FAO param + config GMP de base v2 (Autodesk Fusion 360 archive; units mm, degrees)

design "FAO param + config GMP de base" references "brut conf 1", "Configuration 2", "Configuration 1", "brut conf 2", "brut conf 3", "Configuration 3"
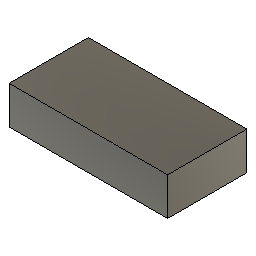
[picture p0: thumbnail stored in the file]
component_insert "Insertion d'un composant1"
component_insert "Insertion d'un composant2"
component_insert "Insertion d'un composant3"
component_insert "Insertion d'un composant4"
component_insert "Insertion d'un composant5"
component_insert "Insertion d'un composant6"

design "Configuration 2"
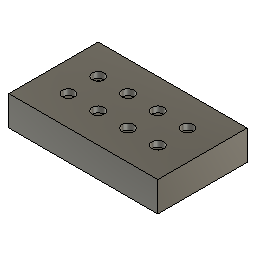
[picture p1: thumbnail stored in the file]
parameter "longueur" = 100
parameter "largeur" = 60
parameter "hauteurext" = 20
parameter "dlamage" = 8
sketch "Esquisse1" plane through (0, 0, 0) normal (0, 0, 1) x axis (1, 0, 0)
  line L1 (-50, -30) -> (50, -30)
  line L2 (-50, 30) -> (-50, -30)
  line L3 (50, 30) -> (-50, 30)
  line L4 (50, -30) -> (50, 30)
  line L5 (-50, 30) -> (50, -30)
  line L6 (50, 30) -> (-50, -30)
  point P6 (0, 0)
  point P1 (0, 0)
  point P4 (-50, 30)
  point P5 (50, 30)
  point P3 (-50, -30)
  horizontal L1
  perpendicular L1 L2
  parallel L1 L3
  parallel L2 L4
  coincident L5 P6
  coincident L6 P6
  coincident P1 P6
  dimension "d3" distance P4 P5 = 100 (= "longueur")
  dimension "d4" distance P3 P4 = 60 (= "largeur")
extrude "Extrusion" new body sketch "Esquisse1" profile of L1 L2 L3 L4 along normal blind 20 (= "hauteurext") named "hauteur"
sketch "Esquisse2" plane through (0, 0, 20) normal (0, 0, 1) x axis (-1, 0, 0)
  line L1 (50, -30) -> (-50, -30)
  line L2 (50, 30) -> (50, -30)
  point P2 (30, -10)
  dimension "d8" distance P2 L1 = 20
  dimension "d9" distance P2 L2 = 20
  dimension "d12" R-Pattern1-uDistance = -20 (= "-( longueur - 40 mm ) / ( nb_de_trous - 1 )")
  dimension "d13" R-Pattern1-vDistance = 20 (= "( largeur - 40 mm ) / ( floor(nb_de_trous) / 2 - 1 )")
hole "Perçage1" HoleDiameter 4 (= "dlamage / 2") CBDepth 4 (= "hauteurext / 5") CBDiameter 8 (= "dlamage") named "dlam"
hole "Perçage2" HoleDiameter 4 (= "dlamage / 2") CBDepth 4 (= "hauteurext / 5") CBDiameter 8 (= "dlamage")
hole "Perçage3" HoleDiameter 4 (= "dlamage / 2") CBDepth 4 (= "hauteurext / 5") CBDiameter 8 (= "dlamage")

design "brut conf 2"
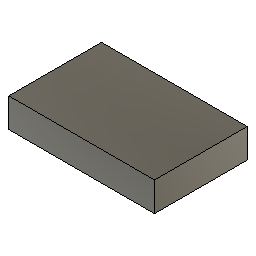
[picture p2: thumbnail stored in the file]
parameter "longueur" = 110
parameter "largeur" = 70
parameter "hauteurext" = 22
parameter "dlamage" = 10
sketch "Esquisse1" plane through (0, 0, 0) normal (0, 0, 1) x axis (1, 0, 0)
  line L1 (-55, -35) -> (55, -35)
  line L2 (-55, 35) -> (-55, -35)
  line L3 (55, 35) -> (-55, 35)
  line L4 (55, -35) -> (55, 35)
  line L5 (-55, 35) -> (55, -35)
  line L6 (55, 35) -> (-55, -35)
  point P6 (0, 0)
  point P1 (0, 0)
  point P4 (-55, 35)
  point P5 (55, 35)
  point P3 (-55, -35)
  horizontal L1
  perpendicular L1 L2
  parallel L1 L3
  parallel L2 L4
  coincident L5 P6
  coincident L6 P6
  coincident P1 P6
  dimension "d3" distance P4 P5 = 110 (= "longueur")
  dimension "d4" distance P3 P4 = 70 (= "largeur")
extrude "Extrusion" new body sketch "Esquisse1" profile of L1 L2 L3 L4 along normal blind 22 (= "hauteurext") named "hauteur"
sketch "Esquisse2" plane through (0, 0, 22) normal (0, 0, 1) x axis (-1, 0, 0)
  line L1 (55, -35) -> (-55, -35)
  line L2 (55, 35) -> (55, -35)
  point P2 (35, -15)
  dimension "d8" distance P2 L1 = 20
  dimension "d9" distance P2 L2 = 20
  dimension "d12" R-Pattern1-uDistance = -17.5 (= "-( longueur - 40 mm ) / ( nb_de_trous - 1 )")
  dimension "d13" R-Pattern1-vDistance = 20 (= "( largeur - 40 mm ) / ( floor(nb_de_trous) / 2 - 1 )")
hole "Perçage1" HoleDiameter 5 (= "dlamage / 2") CBDepth 4.4 (= "hauteurext / 5") CBDiameter 10 (= "dlamage") named "dlam"
hole "Perçage2" HoleDiameter 5 (= "dlamage / 2") CBDepth 4.4 (= "hauteurext / 5") CBDiameter 10 (= "dlamage")
hole "Perçage3" HoleDiameter 5 (= "dlamage / 2") CBDepth 4.4 (= "hauteurext / 5") CBDiameter 10 (= "dlamage")

design "Configuration 3"
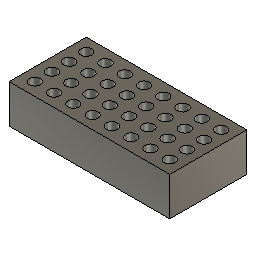
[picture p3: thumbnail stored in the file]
parameter "longueur" = 250
parameter "largeur" = 120
parameter "hauteurext" = 60
parameter "dlamage" = 17
sketch "Esquisse1" plane through (0, 0, 0) normal (0, 0, 1) x axis (1, 0, 0)
  line L1 (-125, -60) -> (125, -60)
  line L2 (-125, 60) -> (-125, -60)
  line L3 (125, 60) -> (-125, 60)
  line L4 (125, -60) -> (125, 60)
  line L5 (-125, 60) -> (125, -60)
  line L6 (125, 60) -> (-125, -60)
  point P6 (0, 0)
  point P1 (0, 0)
  point P4 (-125, 60)
  point P5 (125, 60)
  point P3 (-125, -60)
  horizontal L1
  perpendicular L1 L2
  parallel L1 L3
  parallel L2 L4
  coincident L5 P6
  coincident L6 P6
  coincident P1 P6
  dimension "d3" distance P4 P5 = 250 (= "longueur")
  dimension "d4" distance P3 P4 = 120 (= "largeur")
extrude "Extrusion" new body sketch "Esquisse1" profile of L1 L2 L3 L4 along normal blind 60 (= "hauteurext") named "hauteur"
sketch "Esquisse2" plane through (0, 0, 60) normal (0, 0, 1) x axis (-1, 0, 0)
  line L1 (125, -60) -> (-125, -60)
  line L2 (125, 60) -> (125, -60)
  point P2 (105, -40)
  dimension "d8" distance P2 L1 = 20
  dimension "d9" distance P2 L2 = 20
  dimension "d12" R-Pattern1-uDistance = -30 (= "-( longueur - 40 mm ) / ( nb_de_trous - 1 )")
  dimension "d13" R-Pattern1-vDistance = 26.6667 (= "( largeur - 40 mm ) / ( floor(nb_de_trous) / 2 - 1 )")
hole "Perçage1" HoleDiameter 8.5 (= "dlamage / 2") CBDepth 12 (= "hauteurext / 5") CBDiameter 17 (= "dlamage") named "dlam"
hole "Perçage2" HoleDiameter 8.5 (= "dlamage / 2") CBDepth 12 (= "hauteurext / 5") CBDiameter 17 (= "dlamage")
hole "Perçage3" HoleDiameter 8.5 (= "dlamage / 2") CBDepth 12 (= "hauteurext / 5") CBDiameter 17 (= "dlamage")

design "brut conf 3"
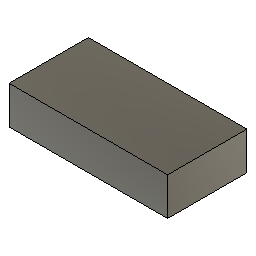
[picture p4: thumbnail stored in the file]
parameter "longueur" = 260
parameter "largeur" = 130
parameter "hauteurext" = 62
parameter "dlamage" = 10
sketch "Esquisse1" plane through (0, 0, 0) normal (0, 0, 1) x axis (1, 0, 0)
  line L1 (-130, -65) -> (130, -65)
  line L2 (-130, 65) -> (-130, -65)
  line L3 (130, 65) -> (-130, 65)
  line L4 (130, -65) -> (130, 65)
  line L5 (-130, 65) -> (130, -65)
  line L6 (130, 65) -> (-130, -65)
  point P6 (0, 0)
  point P1 (0, 0)
  point P4 (-130, 65)
  point P5 (130, 65)
  point P3 (-130, -65)
  horizontal L1
  perpendicular L1 L2
  parallel L1 L3
  parallel L2 L4
  coincident L5 P6
  coincident L6 P6
  coincident P1 P6
  dimension "d3" distance P4 P5 = 260 (= "longueur")
  dimension "d4" distance P3 P4 = 130 (= "largeur")
extrude "Extrusion" new body sketch "Esquisse1" profile of L1 L2 L3 L4 along normal blind 62 (= "hauteurext") named "hauteur"
sketch "Esquisse2" plane through (0, 0, 62) normal (0, 0, 1) x axis (-1, 0, 0)
  line L1 (130, -65) -> (-130, -65)
  line L2 (130, 65) -> (130, -65)
  point P2 (110, -45)
  dimension "d8" distance P2 L1 = 20
  dimension "d9" distance P2 L2 = 20
  dimension "d12" R-Pattern1-uDistance = -55 (= "-( longueur - 40 mm ) / ( nb_de_trous - 1 )")
  dimension "d13" R-Pattern1-vDistance = 60 (= "( largeur - 40 mm ) / ( floor(nb_de_trous) / 2 - 1 )")
hole "Perçage1" HoleDiameter 5 (= "dlamage / 2") CBDepth 12.4 (= "hauteurext / 5") CBDiameter 10 (= "dlamage") named "dlam"
hole "Perçage2" HoleDiameter 5 (= "dlamage / 2") CBDepth 12.4 (= "hauteurext / 5") CBDiameter 10 (= "dlamage")
hole "Perçage3" HoleDiameter 5 (= "dlamage / 2") CBDepth 12.4 (= "hauteurext / 5") CBDiameter 10 (= "dlamage")

design "brut conf 1"
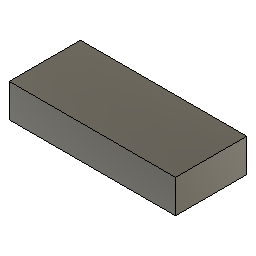
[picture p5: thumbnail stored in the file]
parameter "longueur" = 210
parameter "largeur" = 90
parameter "hauteurext" = 42
parameter "dlamage" = 10
sketch "Esquisse1" plane through (0, 0, 0) normal (0, 0, 1) x axis (1, 0, 0)
  line L1 (-105, -45) -> (105, -45)
  line L2 (-105, 45) -> (-105, -45)
  line L3 (105, 45) -> (-105, 45)
  line L4 (105, -45) -> (105, 45)
  line L5 (-105, 45) -> (105, -45)
  line L6 (105, 45) -> (-105, -45)
  point P6 (0, 0)
  point P1 (0, 0)
  point P4 (-105, 45)
  point P5 (105, 45)
  point P3 (-105, -45)
  horizontal L1
  perpendicular L1 L2
  parallel L1 L3
  parallel L2 L4
  coincident L5 P6
  coincident L6 P6
  coincident P1 P6
  dimension "d3" distance P4 P5 = 210 (= "longueur")
  dimension "d4" distance P3 P4 = 90 (= "largeur")
extrude "Extrusion" new body sketch "Esquisse1" profile of L1 L2 L3 L4 along normal blind 42 (= "hauteurext") named "hauteur"
sketch "Esquisse2" plane through (0, 0, 42) normal (0, 0, 1) x axis (-1, 0, 0)
  line L1 (105, -45) -> (-105, -45)
  line L2 (105, 45) -> (105, -45)
  point P2 (85, -25)
  dimension "d8" distance P2 L1 = 20
  dimension "d9" distance P2 L2 = 20
  dimension "d12" R-Pattern1-uDistance = -42.5 (= "-( longueur - 40 mm ) / ( nb_de_trous - 1 )")
  dimension "d13" R-Pattern1-vDistance = 33.3333 (= "( largeur - 40 mm ) / ( floor(nb_de_trous) / 2 - 1 )")
hole "Perçage1" HoleDiameter 5 (= "dlamage / 2") CBDepth 8.4 (= "hauteurext / 5") CBDiameter 10 (= "dlamage") named "dlam"
hole "Perçage2" HoleDiameter 5 (= "dlamage / 2") CBDepth 8.4 (= "hauteurext / 5") CBDiameter 10 (= "dlamage")
hole "Perçage3" HoleDiameter 5 (= "dlamage / 2") CBDepth 8.4 (= "hauteurext / 5") CBDiameter 10 (= "dlamage")

design "Configuration 1"
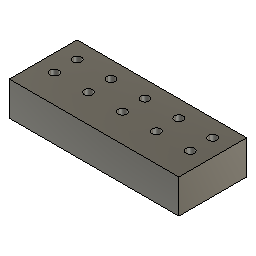
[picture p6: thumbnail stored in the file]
parameter "longueur" = 200
parameter "largeur" = 80
parameter "hauteurext" = 40
parameter "dlamage" = 10
sketch "Esquisse1" plane through (0, 0, 0) normal (0, 0, 1) x axis (1, 0, 0)
  line L1 (-100, -40) -> (100, -40)
  line L2 (-100, 40) -> (-100, -40)
  line L3 (100, 40) -> (-100, 40)
  line L4 (100, -40) -> (100, 40)
  line L5 (-100, 40) -> (100, -40)
  line L6 (100, 40) -> (-100, -40)
  point P6 (0, 0)
  point P1 (0, 0)
  point P4 (-100, 40)
  point P5 (100, 40)
  point P3 (-100, -40)
  horizontal L1
  perpendicular L1 L2
  parallel L1 L3
  parallel L2 L4
  coincident L5 P6
  coincident L6 P6
  coincident P1 P6
  dimension "d3" distance P4 P5 = 200 (= "longueur")
  dimension "d4" distance P3 P4 = 80 (= "largeur")
extrude "Extrusion" new body sketch "Esquisse1" profile of L1 L2 L3 L4 along normal blind 40 (= "hauteurext") named "hauteur"
sketch "Esquisse2" plane through (0, 0, 40) normal (0, 0, 1) x axis (-1, 0, 0)
  line L1 (100, -40) -> (-100, -40)
  line L2 (100, 40) -> (100, -40)
  point P2 (80, -20)
  dimension "d8" distance P2 L1 = 20
  dimension "d9" distance P2 L2 = 20
  dimension "d12" R-Pattern1-uDistance = -40 (= "-( longueur - 40 mm ) / ( nb_de_trous - 1 )")
  dimension "d13" R-Pattern1-vDistance = 26.6667 (= "( largeur - 40 mm ) / ( floor(nb_de_trous) / 2 - 1 )")
hole "Perçage1" HoleDiameter 5 (= "dlamage / 2") CBDepth 8 (= "hauteurext / 5") CBDiameter 10 (= "dlamage") named "dlam"
hole "Perçage2" HoleDiameter 5 (= "dlamage / 2") CBDepth 8 (= "hauteurext / 5") CBDiameter 10 (= "dlamage")
hole "Perçage3" HoleDiameter 5 (= "dlamage / 2") CBDepth 8 (= "hauteurext / 5") CBDiameter 10 (= "dlamage")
